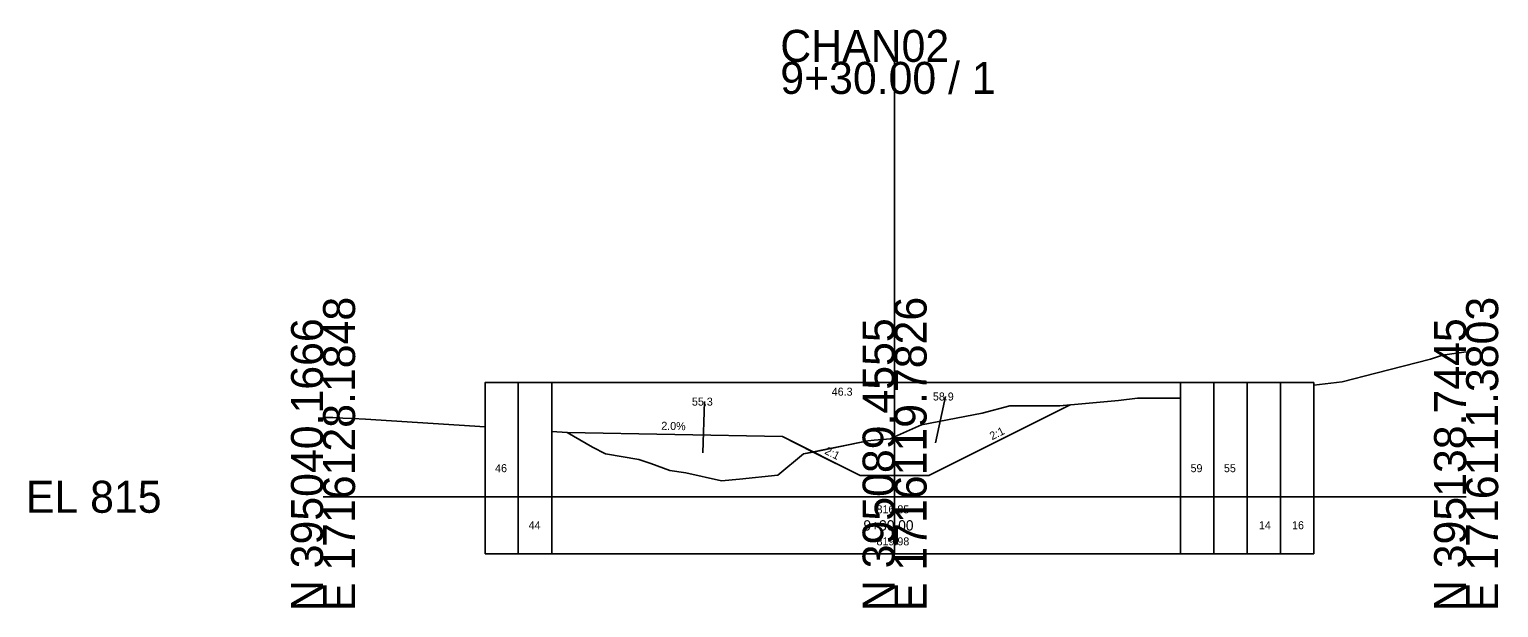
# Model space of a CAD drawing. Extents: x -26 to 103, y -10 to 16052.
# Drawn here: x -25.7 to 102.8, y 2990.3 to 3040.9 of the extents above; entities that cross this region are included whole.
import ezdxf

# ---------------------------------------------------------------- set-up
doc = ezdxf.new("R2010")
doc.units = 0
for name, color, linetype in [('GK_Cells', 7, 'Continuous'), ('SH_Text', 7, 'Continuous'), ('XS_P_Annotation', 7, 'Continuous'), ('XS_P_Boundary', 7, 'Continuous'), ('XS_P_Earthwork_Shapes', 7, 'Continuous'), ('XS_P_Finished_Grade', 7, 'Continuous'), ('XS_X_Ground_Line', 7, 'Continuous')]:
    doc.layers.add(name, color=color, linetype=linetype)

msp = doc.modelspace()

# ---------------------------------------------------------------- linework, layer by layer
at = {"layer": 'GK_Cells'}
for p, q in [((50, 3000), (50, 3038.03)), ((0, 3000), (50, 3000)), ((50, 3000), (100, 3000))]:
    msp.add_line(p, q, dxfattribs=at)
at = {"layer": 'XS_P_Boundary'}
for p, q in [((17.08, 2995.01), (17.08, 3009.99)), ((20, 2995.01), (20, 3009.99)), ((50, 2995.01), (50, 3009.99)), ((75, 2995.01), (75, 3009.99)), ((77.92, 2995.01), (77.92, 3009.99)), ((80.83, 2995.01), (80.83, 3009.99)), ((83.75, 2995.01), (83.75, 3009.99)), ((15.63, 3002.5), (15.63, 3002.5)), ((76.46, 3002.5), (76.46, 3002.5)), ((79.38, 3002.5), (79.38, 3002.5)), ((18.54, 2997.51), (18.54, 2997.51)), ((82.29, 2997.51), (82.29, 2997.51)), ((85.21, 2997.51), (85.21, 2997.51))]:
    msp.add_line(p, q, dxfattribs=at)
msp.add_lwpolyline([(14.17, 2995.01), (14.17, 3009.99), (86.67, 3009.99), (86.67, 2995.01)], close=True, dxfattribs=at)
at = {"layer": 'XS_P_Earthwork_Shapes'}
for p, q in [((33.21, 3003.83), (33.37, 3008.32)), ((53, 3001.85), (65.35, 3008.03)), ((53.57, 3004.71), (54.45, 3008.77)), ((65.35, 3008.03), (64.44, 3007.94)), ((40.19, 3005.26), (21.36, 3005.63)), ((42.87, 3003.91), (40.19, 3005.26)), ((42.87, 3003.91), (47, 3001.85)), ((47, 3001.85), (53, 3001.85))]:
    msp.add_line(p, q, dxfattribs=at)
for points in [[(21.36, 3005.63), (40.19, 3005.26), (47, 3001.85), (53, 3001.85), (65.35, 3008.03)], [(64.44, 3007.94), (60.08, 3007.95), (57.65, 3007.32), (52.34, 3006.29), (50, 3005.24), (49.63, 3005.07), (48.21, 3004.95), (47.66, 3004.9), (42.87, 3003.91)], [(21.36, 3005.63), (23.58, 3004.34), (24.71, 3003.75), (27.63, 3003.25), (28.67, 3002.9), (30.35, 3002.31), (31.73, 3002.08), (34.87, 3001.39), (36.43, 3001.55), (39.79, 3001.88), (42.04, 3003.74), (42.87, 3003.91)]]:
    msp.add_lwpolyline(points, dxfattribs=at)
at = {"layer": 'XS_P_Finished_Grade'}
for p, q in [((65.35, 3008.03), (53, 3001.85)), ((40.19, 3005.26), (21.36, 3005.63)), ((40.19, 3005.26), (47, 3001.85)), ((47, 3001.85), (53, 3001.85))]:
    msp.add_line(p, q, dxfattribs=at)
at = {"layer": 'XS_X_Ground_Line'}
for points in [[(86.67, 3009.76), (89.15, 3010.06), (92.09, 3010.8), (96.87, 3012.02), (97.92, 3012.38), (100, 3012.68)], [(20, 3005.72), (21.36, 3005.63), (23.58, 3004.34), (24.71, 3003.75), (27.63, 3003.25), (28.67, 3002.9), (30.35, 3002.31), (31.73, 3002.08), (34.87, 3001.39), (36.43, 3001.55), (39.79, 3001.88), (42.04, 3003.74), (47.66, 3004.9), (48.21, 3004.95), (49.63, 3005.07), (50, 3005.24), (52.34, 3006.29), (57.65, 3007.32), (60.08, 3007.95), (64.44, 3007.94), (69.59, 3008.43), (71.24, 3008.62), (75, 3008.63)], [(0, 3006.94), (0.85, 3006.92), (1.72, 3006.88), (2.58, 3006.85), (3.71, 3006.79), (14.17, 3006.11)]]:
    msp.add_lwpolyline(points, dxfattribs=at)

# ---------------------------------------------------------------- texts
at = {"layer": 'GK_Cells'}
for s, p in [('CHAN02', (40, 3038.03)), ('9+30.00 / 1', (40, 3035.23)), ('EL 815', (-26, 2998.6))]:
    msp.add_text(s, height=2.8, dxfattribs=at).set_placement(p)
for s, p in [('E 1716128.1848', (2.8, 2990)), ('E 1716119.7826', (52.8, 2990)), ('E 1716111.3803', (102.8, 2990)), ('N 395040.1666', (0, 2990)), ('N 395089.4555', (50, 2990)), ('N 395138.7445', (100, 2990))]:
    msp.add_text(s, height=2.8, rotation=90, dxfattribs=at).set_placement(p)
at = {"layer": 'SH_Text'}
for s, p in [('46', (15.05, 3002.15)), ('59', (75.89, 3002.15)), ('55', (78.81, 3002.15)), ('44', (17.98, 2997.16)), ('14', (81.87, 2997.16)), ('16', (84.77, 2997.16))]:
    msp.add_text(s, height=0.7, dxfattribs=at).set_placement(p)
at = {"layer": 'XS_P_Annotation'}
for s, rotation, p in [('2.0%', 358.8542, (29.58, 3005.86)), ('2:1', 26.5651, (58.53, 3004.94)), ('2:1', 333.4349, (43.82, 3003.79))]:
    msp.add_text(s, height=0.7, rotation=rotation, dxfattribs=at).set_placement(p)
for s, height, p in [('816.85', 0.7, (48.42, 2998.55)), ('9+30.00', 0.9, (47.27, 2997.05)), ('819.98', 0.7, (48.42, 2995.75))]:
    msp.add_text(s, height=height, dxfattribs=at).set_placement(p)
at = {"layer": 'XS_P_Earthwork_Shapes'}
for s, p in [('46.3', (44.5, 3008.84)), ('58.9', (53.35, 3008.42)), ('55.3', (32.27, 3007.97))]:
    msp.add_text(s, height=0.7, dxfattribs=at).set_placement(p)

doc.saveas('drawing.dxf')
